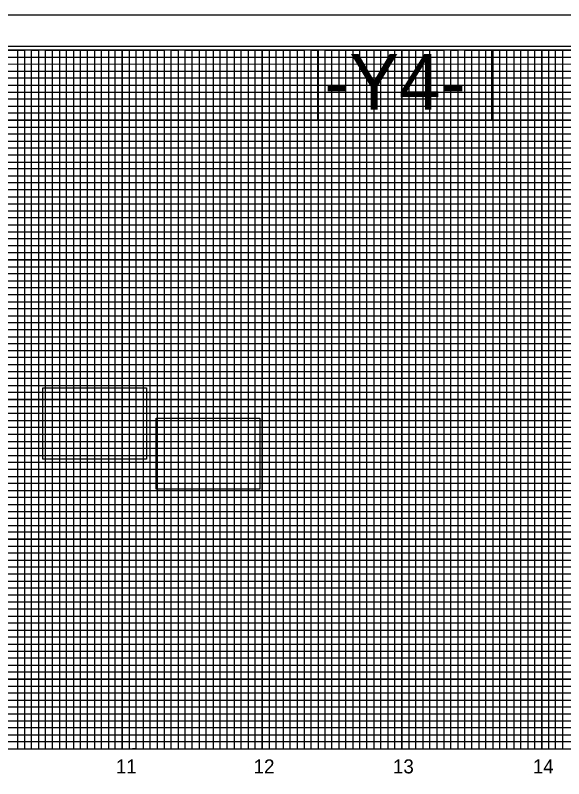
# Model space of a CAD drawing. Extents: x 1779926 to 1781626, y 618464 to 619564.
# Drawn here: x 1780866 to 1781259, y 619018 to 619564 of the extents above; entities that cross this region are included whole.
import ezdxf

# ---------------------------------------------------------------- set-up
doc = ezdxf.new("R2010")
doc.units = 0
for name, color, linetype in [('Exist Vertical Profile Horizontal Axis Label Major', 7, 'Continuous'), ('Prop DSN Text', 7, 'Continuous'), ('Prop Grid Mask', 7, 'Continuous'), ('Sheet DOT Grid CELL', 7, 'Continuous'), ('Sheet Layout Profile Border Port 1', 7, 'Continuous'), ('Sheet Plot Border Inside CELL', 7, 'Continuous'), ('Sheet Plot Border Outside CELL', 7, 'Continuous'), ('Sheet Profile CELL', 7, 'Continuous'), ('Sheet Profile Grid Major CELL', 7, 'Continuous'), ('Sheet Profile Grid Middle CELL', 7, 'Continuous'), ('Sheet Profile Grid Minor CELL', 7, 'Continuous')]:
    doc.layers.add(name, color=color, linetype=linetype)

msp = doc.modelspace()

# ---------------------------------------------------------------- linework, layer by layer
at = {"layer": 'Prop Grid Mask'}
for points in [[(1781207.22, 619539.19), (1781082.61, 619539.19), (1781082.61, 619489.19), (1781207.22, 619489.19)], [(1780886.09, 619297.5), (1780960.34, 619297.5), (1780960.34, 619246.59), (1780886.09, 619246.59)], [(1780967.2, 619275.96), (1781041.45, 619275.96), (1781041.45, 619225.05), (1780967.2, 619225.05)]]:
    msp.add_lwpolyline(points, close=True, dxfattribs=at)
at = {"layer": 'Sheet DOT Grid CELL'}
for p, q in [((1780892.96, 619039.19), (1780892.96, 619539.19)), ((1780942.96, 619039.19), (1780942.96, 619539.19)), ((1780992.96, 619039.19), (1780992.96, 619539.19)), ((1781042.96, 619039.19), (1781042.96, 619539.19)), ((1781092.96, 619039.19), (1781092.96, 619539.19)), ((1781142.96, 619039.19), (1781142.96, 619539.19)), ((1781192.96, 619039.19), (1781192.96, 619539.19)), ((1781242.96, 619039.19), (1781242.96, 619539.19)), ((1781392.91, 619489.19), (1780092.96, 619489.19)), ((1781392.91, 619439.19), (1780092.96, 619439.19)), ((1781392.96, 619389.19), (1780092.96, 619389.19)), ((1781392.91, 619339.19), (1780092.96, 619339.19)), ((1781592.96, 619289.19), (1780092.96, 619289.19)), ((1781592.96, 619239.19), (1780092.96, 619239.19)), ((1781592.96, 619189.19), (1780092.96, 619189.19)), ((1781592.96, 619139.19), (1780092.96, 619139.19)), ((1781592.96, 619089.19), (1780092.96, 619089.19))]:
    msp.add_line(p, q, dxfattribs=at)
at = {"layer": 'Sheet Layout Profile Border Port 1'}
for points in [[(1781542.96, 619099.19), (1781542.96, 619314.19), (1781392.91, 619314.19), (1781392.96, 619539.19), (1780142.96, 619539.19), (1780142.96, 619039.19), (1781542.96, 619039.19), (1781542.96, 619049.19)], [(1780142.96, 619378.14), (1780142.96, 619039.19), (1781542.96, 619039.19), (1781542.96, 619314.19)]]:
    msp.add_lwpolyline(points, dxfattribs=at)
at = {"layer": 'Sheet Plot Border Inside CELL'}
msp.add_lwpolyline([(1779938.96, 618486.64), (1781605.46, 618486.64), (1781605.46, 619541.74), (1779938.96, 619541.74)], close=True, dxfattribs=at)
at = {"layer": 'Sheet Plot Border Outside CELL'}
msp.add_lwpolyline([(1779925.96, 618464.19), (1781625.96, 618464.19), (1781625.96, 619564.19), (1779925.96, 619564.19)], close=True, dxfattribs=at)
at = {"layer": 'Sheet Profile CELL'}
msp.add_line((1780092.96, 619039.19), (1781592.96, 619039.19), dxfattribs=at)
msp.add_lwpolyline([(1781592.96, 619539.19), (1780092.96, 619539.19), (1780092.96, 618489.19), (1781592.96, 618489.19)], close=True, dxfattribs=at)
at = {"layer": 'Sheet Profile Grid Major CELL'}
for points in [[(1780842.96, 619039.19), (1780892.96, 619039.19), (1780892.96, 619539.19), (1780942.96, 619539.19), (1780942.96, 619039.19), (1780992.96, 619039.19), (1780992.96, 619539.19), (1781042.96, 619539.19), (1781042.96, 619039.19), (1781092.96, 619039.19), (1781092.96, 619539.19), (1781142.96, 619539.19), (1781142.96, 619039.19), (1781192.96, 619039.19), (1781192.96, 619539.19), (1781242.96, 619539.19), (1781242.96, 619039.19), (1781292.96, 619039.19), (1781292.96, 619539.19), (1781342.96, 619539.19), (1781342.96, 619039.19), (1781392.96, 619039.19), (1781392.96, 619539.19), (1781419.26, 619539.19)], [(1780092.96, 619489.19), (1781392.96, 619489.19)], [(1781392.96, 619439.19), (1780092.96, 619439.19), (1780092.96, 619389.19), (1781392.96, 619389.19)], [(1781392.96, 619339.19), (1780092.96, 619339.19), (1780092.96, 619289.19), (1781592.96, 619289.19)], [(1781592.96, 619239.19), (1780092.96, 619239.19), (1780092.96, 619189.19), (1781592.96, 619189.19)], [(1781592.96, 619139.19), (1780092.96, 619139.19), (1780092.96, 619139.19), (1780092.96, 619089.19), (1781592.96, 619089.19)]]:
    msp.add_lwpolyline(points, dxfattribs=at)
at = {"layer": 'Sheet Profile Grid Middle CELL'}
msp.add_line((1780092.96, 619514.19), (1781392.91, 619514.19), dxfattribs=at)
for points in [[(1780817.96, 619539.19), (1780867.96, 619539.19), (1780867.96, 619039.19), (1780917.96, 619039.19), (1780917.96, 619539.19), (1780967.96, 619539.19), (1780967.96, 619039.19), (1781017.96, 619039.19), (1781017.96, 619539.19), (1781067.96, 619539.19), (1781067.96, 619039.19), (1781117.96, 619039.19), (1781117.96, 619539.19), (1781167.96, 619539.19), (1781167.96, 619039.19), (1781217.96, 619039.19), (1781217.96, 619539.19), (1781267.96, 619539.19)], [(1781392.96, 619464.19), (1780092.96, 619464.19), (1780092.96, 619414.19), (1781392.96, 619414.19)], [(1781392.91, 619364.19), (1780092.96, 619364.19), (1780092.96, 619314.19), (1781417.96, 619314.19)], [(1781592.96, 619264.19), (1780092.96, 619264.19), (1780092.96, 619214.19), (1781592.96, 619214.19)], [(1781592.96, 619164.19), (1780092.96, 619164.19), (1780092.96, 619114.19), (1781592.96, 619114.19)], [(1781592.96, 619064.19), (1780092.96, 619064.19)]]:
    msp.add_lwpolyline(points, dxfattribs=at)
at = {"layer": 'Sheet Profile Grid Minor CELL'}
for p, q in [((1780142.96, 619534.19), (1781392.96, 619534.19)), ((1781392.96, 619529.19), (1780142.96, 619528.84)), ((1780142.96, 619524.19), (1781392.96, 619524.19)), ((1781392.91, 619404.19), (1780142.96, 619404.19)), ((1781392.96, 619399.19), (1780142.96, 619399.19)), ((1781392.96, 619394.19), (1780142.96, 619394.19)), ((1780142.96, 619384.19), (1781392.96, 619384.19)), ((1781392.96, 619379.19), (1780142.96, 619379.19)), ((1780142.96, 619374.19), (1781392.91, 619374.19)), ((1781392.91, 619354.19), (1780142.96, 619354.19)), ((1780142.96, 619349.19), (1781392.91, 619349.19)), ((1781392.91, 619329.19), (1780142.96, 619329.19)), ((1780142.96, 619324.19), (1781392.91, 619324.19)), ((1781542.96, 619304.19), (1780142.96, 619304.19)), ((1780142.96, 619299.19), (1781542.96, 619299.19)), ((1781542.96, 619294.19), (1780142.96, 619294.19)), ((1780142.96, 619284.19), (1781542.96, 619284.19)), ((1781542.96, 619279.19), (1780142.96, 619279.19)), ((1780142.96, 619274.19), (1781542.96, 619274.19)), ((1781542.96, 619269.19), (1780142.96, 619269.19)), ((1780142.96, 619259.19), (1781542.96, 619259.19)), ((1781542.96, 619254.19), (1780142.96, 619254.19)), ((1780142.96, 619249.19), (1781542.96, 619249.19)), ((1781542.96, 619244.19), (1780142.96, 619244.19)), ((1780142.96, 619234.19), (1781542.96, 619234.19)), ((1781542.96, 619229.19), (1780142.96, 619229.19)), ((1780142.96, 619224.19), (1781542.96, 619224.19)), ((1781542.96, 619219.19), (1780142.96, 619219.19)), ((1780142.96, 619209.19), (1781542.96, 619209.19)), ((1781542.96, 619204.19), (1780142.96, 619204.19)), ((1780142.96, 619199.19), (1781542.96, 619199.19)), ((1781542.96, 619194.19), (1780142.96, 619194.19)), ((1780142.96, 619184.19), (1781542.96, 619184.19)), ((1781542.96, 619179.19), (1780142.96, 619179.19)), ((1780142.96, 619174.19), (1781542.96, 619174.19)), ((1781542.96, 619169.19), (1780142.96, 619169.19)), ((1780142.96, 619159.19), (1781542.96, 619159.19)), ((1781542.96, 619154.19), (1780142.96, 619154.19)), ((1781542.96, 619149.19), (1780142.96, 619149.19)), ((1781542.96, 619144.19), (1780142.96, 619144.19)), ((1780142.96, 619134.19), (1781542.96, 619134.19)), ((1781542.96, 619129.19), (1780142.96, 619129.19)), ((1780142.96, 619124.19), (1781542.96, 619124.19)), ((1781542.96, 619119.19), (1780142.96, 619119.19)), ((1780142.96, 619109.19), (1781542.96, 619109.19)), ((1781542.96, 619104.19), (1780142.96, 619104.19)), ((1780142.96, 619099.19), (1781542.96, 619099.19)), ((1781542.96, 619094.19), (1780142.96, 619094.19)), ((1780142.96, 619084.19), (1781542.96, 619084.19)), ((1781542.96, 619079.19), (1780142.96, 619079.19)), ((1780142.96, 619074.19), (1781542.96, 619074.19)), ((1781542.96, 619069.19), (1780142.96, 619069.19)), ((1780142.96, 619059.19), (1781542.96, 619059.19)), ((1781542.96, 619054.19), (1780142.96, 619054.19)), ((1780142.96, 619049.19), (1781542.96, 619049.19))]:
    msp.add_line(p, q, dxfattribs=at)
for points in [[(1780862.96, 619539.19), (1780872.96, 619539.19), (1780872.96, 619039.19), (1780877.96, 619039.19), (1780877.96, 619539.19), (1780882.96, 619539.19), (1780882.96, 619039.19), (1780887.96, 619039.19), (1780887.96, 619539.19), (1780897.96, 619539.19), (1780897.96, 619039.19), (1780902.96, 619039.19), (1780902.96, 619539.19), (1780907.96, 619539.19), (1780907.96, 619039.19), (1780912.96, 619039.19), (1780912.96, 619539.19), (1780922.96, 619539.19), (1780922.96, 619039.19), (1780927.96, 619039.19), (1780927.96, 619539.19), (1780932.96, 619539.19), (1780932.96, 619039.19), (1780937.96, 619039.19), (1780937.96, 619539.19), (1780947.96, 619539.19), (1780947.96, 619039.19), (1780952.66, 619039.74), (1780952.96, 619039.19), (1780952.96, 619539.19), (1780957.96, 619539.19), (1780957.96, 619039.19), (1780962.96, 619039.19), (1780962.96, 619539.19), (1780972.96, 619539.19), (1780972.96, 619039.19), (1780977.96, 619039.19)], [(1780977.96, 619039.19), (1780977.96, 619539.19), (1780982.96, 619539.19), (1780982.96, 619039.19), (1780987.96, 619039.19), (1780987.96, 619539.19), (1780997.96, 619539.19), (1780997.96, 619039.19), (1781002.96, 619039.19), (1781002.96, 619539.19), (1781007.96, 619539.19), (1781007.96, 619039.19), (1781012.96, 619039.19), (1781012.96, 619539.19), (1781022.96, 619539.19), (1781022.96, 619039.19), (1781027.96, 619039.19), (1781027.96, 619539.19), (1781032.96, 619539.19), (1781032.96, 619039.19), (1781037.96, 619039.19), (1781037.96, 619539.19), (1781047.96, 619539.19), (1781047.96, 619039.19), (1781052.96, 619039.19), (1781052.96, 619539.19), (1781057.96, 619539.19), (1781057.96, 619039.19), (1781062.96, 619039.19), (1781062.96, 619539.19), (1781072.96, 619539.19), (1781072.96, 619039.19), (1781077.96, 619039.19), (1781077.96, 619539.19), (1781082.96, 619539.19), (1781082.96, 619039.19), (1781087.96, 619039.19), (1781087.96, 619539.19), (1781097.96, 619539.19), (1781097.96, 619039.19), (1781102.96, 619039.19), (1781102.96, 619539.19), (1781107.96, 619539.19), (1781107.96, 619039.19), (1781112.96, 619039.19), (1781112.96, 619539.19), (1781122.96, 619539.19), (1781122.96, 619039.19), (1781127.96, 619039.19), (1781127.96, 619539.19), (1781132.96, 619539.19), (1781132.96, 619039.19), (1781137.96, 619039.19), (1781137.96, 619539.19), (1781147.96, 619539.19), (1781147.96, 619039.19), (1781152.96, 619039.19), (1781152.96, 619539.19), (1781157.96, 619539.19), (1781157.96, 619039.19), (1781162.96, 619039.19), (1781162.96, 619539.19), (1781172.96, 619539.19), (1781172.96, 619039.19), (1781177.96, 619039.19), (1781177.96, 619539.19), (1781182.96, 619539.19), (1781182.96, 619039.19), (1781187.96, 619039.19), (1781187.96, 619539.19), (1781197.96, 619539.19), (1781197.96, 619039.19), (1781202.96, 619039.19), (1781202.96, 619539.19), (1781207.96, 619539.19), (1781207.96, 619039.19), (1781212.96, 619039.19), (1781212.96, 619539.19), (1781222.96, 619539.19), (1781222.96, 619039.19), (1781227.96, 619039.19), (1781227.96, 619539.19), (1781232.96, 619539.19), (1781232.96, 619039.19), (1781237.96, 619039.19), (1781237.96, 619539.19), (1781247.96, 619539.19), (1781247.96, 619039.19), (1781252.96, 619039.19), (1781252.96, 619539.19), (1781257.96, 619539.19), (1781257.96, 619039.19), (1781262.96, 619039.19)], [(1781392.96, 619519.19), (1780142.96, 619519.19), (1780142.96, 619509.19), (1781392.96, 619509.19)], [(1781392.91, 619504.19), (1780142.96, 619504.19), (1780142.96, 619499.19), (1781392.96, 619499.19)], [(1781392.96, 619494.19), (1780142.96, 619494.19), (1780142.96, 619484.19), (1781392.96, 619484.19)], [(1781392.96, 619479.19), (1780142.96, 619479.19), (1780142.96, 619474.19), (1781392.96, 619474.19)], [(1781392.96, 619469.19), (1780142.96, 619469.19), (1780142.96, 619459.19), (1781392.96, 619459.19)], [(1781392.96, 619454.19), (1780142.96, 619454.19), (1780142.96, 619449.19), (1781392.96, 619449.19)], [(1781392.96, 619444.19), (1780142.96, 619444.19), (1780142.96, 619434.19), (1781392.96, 619434.19)], [(1781392.96, 619429.09), (1780143.06, 619429.09), (1780143.06, 619424.19), (1781392.96, 619424.19)], [(1781392.96, 619419.19), (1780142.96, 619419.19), (1780142.96, 619409.19), (1781392.96, 619409.19)], [(1781392.91, 619369.19), (1780142.96, 619369.19), (1780142.96, 619359.19), (1781392.91, 619359.19)], [(1781392.91, 619344.19), (1780142.96, 619344.19), (1780142.96, 619334.19), (1781392.91, 619334.19)], [(1781392.91, 619319.19), (1780142.96, 619319.19), (1780142.96, 619309.19), (1781542.96, 619309.19)], [(1781542.96, 619044.19), (1780142.96, 619044.19)]]:
    msp.add_lwpolyline(points, dxfattribs=at)

# ---------------------------------------------------------------- texts
at = {"layer": 'Exist Vertical Profile Horizontal Axis Label Major'}
for s, p in [('11', (1780938.38, 619021.69)), ('12', (1781036.93, 619021.69)), ('13', (1781136.61, 619021.69)), ('14', (1781236.66, 619021.69))]:
    msp.add_text(s, height=10, dxfattribs=at).set_placement(p)
at = {"layer": 'Prop DSN Text'}
msp.add_text('-Y4-', height=40, dxfattribs=at).set_placement((1781087.43, 619496.56))

doc.saveas('drawing.dxf')
